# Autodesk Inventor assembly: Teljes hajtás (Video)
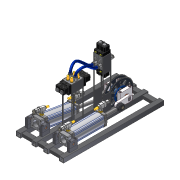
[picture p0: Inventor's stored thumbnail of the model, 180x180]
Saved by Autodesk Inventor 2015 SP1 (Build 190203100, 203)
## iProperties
Created: 2013-02
Part Number: Teljes hajtás (Video)
Document SubType Name: Assembly
Designer: Marci
Author: Marci
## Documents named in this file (19)
- C:\Users\TREINA11\Desktop\#01- Polymechanics and Automation\01 - 3D Models\Pneumatic System\Teljes hajtás (Video).iam
- C:\Users\TREINA11\Desktop\#01- Polymechanics and Automation\01 - 3D Models\Pneumatic System\Váz.iam
- C:\Users\TREINA11\Desktop\#01- Polymechanics and Automation\01 - 3D Models\Pneumatic System\Közdarab.ipt
- C:\Users\TREINA11\Desktop\#01- Polymechanics and Automation\01 - 3D Models\Pneumatic System\1827001604.ipt
- C:\Users\TREINA11\Desktop\#01- Polymechanics and Automation\01 - 3D Models\Pneumatic System\1827001611.ipt
- C:\Users\TREINA11\Desktop\#01- Polymechanics and Automation\01 - 3D Models\Pneumatic System\csapágyház.ipt
- C:\Users\TREINA11\Desktop\#01- Polymechanics and Automation\01 - 3D Models\Pneumatic System\Összerakva a henger.iam
- C:\Users\TREINA11\Desktop\#01- Polymechanics and Automation\01 - 3D Models\Pneumatic System\Főtengely összerakva.iam
- C:\Users\TREINA11\Desktop\#01- Polymechanics and Automation\01 - 3D Models\Pneumatic System\Szelep összerakva.iam
- C:\Users\TREINA11\Desktop\#01- Polymechanics and Automation\01 - 3D Models\Pneumatic System\Szelep.ipt
- C:\Users\TREINA11\Desktop\#01- Polymechanics and Automation\01 - 3D Models\Pneumatic System\1.4 12 gyorscsat.ipt
- C:\Users\TREINA11\Desktop\#01- Polymechanics and Automation\01 - 3D Models\Pneumatic System\Zárócsavar.ipt
- C:\Users\TREINA11\Desktop\#01- Polymechanics and Automation\01 - 3D Models\Pneumatic System\Lemez.ipt
- C:\Users\TREINA11\Desktop\#01- Polymechanics and Automation\01 - 3D Models\Pneumatic System\Lemez 2.ipt
- C:\Users\TREINA11\Desktop\#01- Polymechanics and Automation\01 - 3D Models\Pneumatic System\Teljes hajtás.Tube and Pipe Runs05.iam
- C:\Users\TREINA11\Desktop\#01- Polymechanics and Automation\01 - 3D Models\Pneumatic System\Atuador.iam
- C:\Users\TREINA11\Desktop\#01- Polymechanics and Automation\01 - 3D Models\Pneumatic System\Eixo.ipt
- C:\Users\TREINA11\Desktop\#01- Polymechanics and Automation\01 - 3D Models\Pneumatic System\Ponta.ipt
- C:\Users\TREINA11\Desktop\#01- Polymechanics and Automation\01 - 3D Models\Pneumatic System\DIN 912 - M8 x 1,25 x 30 x 26,875.ipt
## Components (69 placed, 18 different names)
1. Váz:1 [sub-assembly] — Flush:1, Mate:1, Flush:2, Mate:2, Flush:3, Flush:4, Mate:3, Flush:5, Flush:6, Mate:4, Flush:7, Flush:8, Mate:14, Mate:15, Flush:17, Flush:18, Flush:19, Flush:20, Flush:25, Mate:30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
2. Közdarab:1 — Flush:1, Mate:1, Flush:2, Mate:5, Flush:9, Flush:10
3. Közdarab:2 — Mate:2, Flush:3, Flush:4, Mate:6, Flush:11, Flush:12
4. Közdarab:3 — Mate:3, Flush:5, Flush:6, Flush:13, Mate:7, Flush:14
5. Közdarab:4 — Mate:4, Flush:7, Flush:8, Mate:8, Flush:16
6. 1827001604:1 — Mate:5, Flush:9, Flush:10, Mate:12, Mate:13, Inserir:19, Inserir:22
7. 1827001604:2 — Mate:6, Flush:11, Flush:12, Mate:29, Inserir:20, Inserir:21
8. 1827001604:3 — Flush:13, Mate:7, Flush:14, Mate:9, Mate:10, Inserir:23, Inserir:24
9. 1827001604:4 — Mate:8, Flush:16, Mate:11, Inserir:25, Inserir:26
10. 1827001611:1 — Mate:9, Mate:10, Mate:11, Insert:15, Insert:16, Insert:17, Insert:18, Mate:67, Mate:68, Angle:2
11. 1827001611:2 — Mate:12, Mate:13, Mate:59, Mate:60, Angle:1, Insert:2, Insert:3, Insert:4, Insert:5
12. csapágyház:1 — Mate:14, Flush:18, Flush:20, Mate:22, Mate:23, Inserir:29, Inserir:30
13. csapágyház:2 — Mate:15, Flush:17, Flush:19, Inserir:27, Inserir:28
14. Összerakva a henger:1 [sub-assembly] — Mate:61, Mate:62, Mate:63
15. Összerakva a henger:2 [sub-assembly] — Mate:69, Mate:70, Mate:72
16. Főtengely összerakva:1 [sub-assembly] — Mate:22, Mate:23, Mate:65, Mate:71, MOTOR
17. Szelep összerakva:1 [sub-assembly] — Mate:28, Mate:29, Mate:30, Flush:27, Flush:28, Flush:30, Mate:55, Mate:56
18. Szelep összerakva:2 [sub-assembly] — Flush:26, Flush:27, Flush:28, Flush:29, Mate:58
19. Szelep:1 — Flush:31, Mate:31, Flush:32, Mate:34, Mate:35, Mate:36, Mate:38, Mate:40, Mate:42, Mate:44, Mate:47, Mate:48, Mate:51, Mate:54, Flush:34
20. Szelep:2 — Flush:29, Flush:30, Flush:31, Mate:31, Flush:32, Mate:32, Mate:33, Mate:37, Mate:39, Mate:41, Mate:43, Mate:45, Mate:46, Mate:49, Mate:50, Mate:52, Flush:33
21. 1.4 12 gyorscsat:1 — Mate:32, Mate:33
22. 1.4 12 gyorscsat:2 — Mate:34, Mate:35
23. 1.4 12 gyorscsat:3 — Mate:36, Mate:38
24. 1.4 12 gyorscsat:4 — Mate:37, Mate:39
25. Zárócsavar:1 — Mate:46, Mate:49
26. Zárócsavar:2 — Mate:47, Mate:48
27. Zárócsavar:3 — Mate:40, Mate:51
28. Zárócsavar:4 — Mate:41, Mate:50
29. Zárócsavar:5 — Mate:43, Mate:45
30. Zárócsavar:6 — Mate:42, Mate:44
31. Lemez:1 — Mate:52, Flush:33, Mate:53, Flush:35
32. Lemez:2 — Mate:54, Flush:34, Flush:35, Flush:38
33. Lemez 2:1 — Mate:55, Mate:56, Mate:57, Flush:36, Flush:37
34. Lemez 2:2 — Flush:36, Mate:58, Flush:37
35. Tube & Pipe Runs 05 [sub-assembly]
36. Atuador:1 [sub-assembly] — Mate:59, Mate:60, Mate:61, Mate:62, Mate:63, Angle:1, Mate:64, Insert:6, Insert:7, Insert:8, Insert:9, Mate:75
37. Eixo:1 — Mate:64, Insert:1, Mate:75
38. Ponta:1 — Insert:1, Mate:65
39. DIN 912 - M8 x 1,25 x 30 x 26,875:1 — Insert:2
40. DIN 912 - M8 x 1,25 x 30 x 26,875:2 — Insert:3
41. DIN 912 - M8 x 1,25 x 30 x 26,875:3 — Insert:4
42. DIN 912 - M8 x 1,25 x 30 x 26,875:4 — Insert:5
43. DIN 912 - M8 x 1,25 x 30 x 26,875:5 — Insert:6
44. DIN 912 - M8 x 1,25 x 30 x 26,875:6 — Insert:7
45. DIN 912 - M8 x 1,25 x 30 x 26,875:7 — Insert:9
46. DIN 912 - M8 x 1,25 x 30 x 26,875:8 — Insert:8
47. Atuador:2 [sub-assembly] — Mate:67, Mate:68, Mate:69, Mate:70, Angle:2, Mate:72
48. Eixo:2
49. Ponta:2 — Mate:71
50. DIN 912 - M8 x 1,25 x 30 x 26,875:9 — Insert:16
51. DIN 912 - M8 x 1,25 x 30 x 26,875:10 — Insert:17
52. DIN 912 - M8 x 1,25 x 30 x 26,875:11 — Insert:18
53. DIN 912 - M8 x 1,25 x 30 x 26,875:12 — Insert:15
54. DIN 912 - M8 x 1,25 x 30 x 26,875:13
55. DIN 912 - M8 x 1,25 x 30 x 26,875:14
56. DIN 912 - M8 x 1,25 x 30 x 26,875:15
57. DIN 912 - M8 x 1,25 x 30 x 26,875:16
58. DIN 912 - M8 x 1,25 x 30 x 26,875:17 — Inserir:19
59. DIN 912 - M8 x 1,25 x 30 x 26,875:18 — Inserir:23
60. DIN 912 - M8 x 1,25 x 30 x 26,875:19 — Inserir:20
61. DIN 912 - M8 x 1,25 x 30 x 26,875:20 — Inserir:21
62. DIN 912 - M8 x 1,25 x 30 x 26,875:21 — Inserir:22
63. DIN 912 - M8 x 1,25 x 30 x 26,875:22 — Inserir:24
64. DIN 912 - M8 x 1,25 x 30 x 26,875:23 — Inserir:25
65. DIN 912 - M8 x 1,25 x 30 x 26,875:24 — Inserir:26
66. DIN 912 - M8 x 1,25 x 30 x 26,875:25 — Inserir:29
67. DIN 912 - M8 x 1,25 x 30 x 26,875:26 — Inserir:30
68. DIN 912 - M8 x 1,25 x 30 x 26,875:27 — Inserir:27
69. DIN 912 - M8 x 1,25 x 30 x 26,875:28 — Inserir:28
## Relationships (126: Mate 64, Flush 34, Insert 25, Angle 3)
- Flush:1: Váz:1 ↔ Közdarab:1
- Mate:1: Váz:1 ↔ Közdarab:1
- Flush:2: Váz:1 ↔ Közdarab:1
- Mate:2: Váz:1 ↔ Közdarab:2
- Flush:3: Váz:1 ↔ Közdarab:2
- Flush:4: Váz:1 ↔ Közdarab:2
- Mate:3: Váz:1 ↔ Közdarab:3
- Flush:5: Váz:1 ↔ Közdarab:3
- Flush:6: Váz:1 ↔ Közdarab:3
- Mate:4: Váz:1 ↔ Közdarab:4
- Flush:7: Váz:1 ↔ Közdarab:4
- Flush:8: Váz:1 ↔ Közdarab:4
- Mate:5: Közdarab:1 ↔ 1827001604:1
- Flush:9: Közdarab:1 ↔ 1827001604:1
- Flush:10: Közdarab:1 ↔ 1827001604:1
- Mate:6: Közdarab:2 ↔ 1827001604:2
- Flush:11: Közdarab:2 ↔ 1827001604:2
- Flush:12: Közdarab:2 ↔ 1827001604:2
- Flush:13: Közdarab:3 ↔ 1827001604:3
- Mate:7: Közdarab:3 ↔ 1827001604:3
- Flush:14: Közdarab:3 ↔ 1827001604:3
- Mate:8: Közdarab:4 ↔ 1827001604:4
- Flush:16: Közdarab:4 ↔ 1827001604:4
- Mate:9: 1827001604:3 ↔ 1827001611:1
- Mate:10: 1827001604:3 ↔ 1827001611:1
- Mate:11: 1827001604:4 ↔ 1827001611:1
- Mate:12: 1827001604:1 ↔ 1827001611:2
- Mate:13: 1827001604:1 ↔ 1827001611:2
- Mate:14: Váz:1 ↔ csapágyház:1
- Mate:15: Váz:1 ↔ csapágyház:2
- Flush:17: Váz:1 ↔ csapágyház:2
- Flush:18: Váz:1 ↔ csapágyház:1
- Flush:19: Váz:1 ↔ csapágyház:2
- Flush:20: Váz:1 ↔ csapágyház:1
- Mate:22: csapágyház:1 ↔ Főtengely összerakva:1
- Mate:23: csapágyház:1 ↔ Főtengely összerakva:1
- Flush:25: Váz:1
- Mate:28: Szelep összerakva:1
- Mate:29: 1827001604:2 ↔ Szelep összerakva:1
- Mate:30: Váz:1 ↔ Szelep összerakva:1
- Flush:26: Szelep összerakva:2
- Flush:27: Szelep összerakva:1 ↔ Szelep összerakva:2
- Flush:28: Szelep összerakva:1 ↔ Szelep összerakva:2
- Flush:29: Szelep összerakva:2 ↔ Szelep:2
- Flush:30: Szelep összerakva:1 ↔ Szelep:2
- Flush:31: Szelep:1 ↔ Szelep:2
- Mate:31: Szelep:1 ↔ Szelep:2
- Flush:32: Szelep:1 ↔ Szelep:2
- Mate:32: Szelep:2 ↔ 1.4 12 gyorscsat:1
- Mate:33: Szelep:2 ↔ 1.4 12 gyorscsat:1
- Mate:34: Szelep:1 ↔ 1.4 12 gyorscsat:2
- Mate:35: Szelep:1 ↔ 1.4 12 gyorscsat:2
- Mate:36: Szelep:1 ↔ 1.4 12 gyorscsat:3
- Mate:37: Szelep:2 ↔ 1.4 12 gyorscsat:4
- Mate:38: Szelep:1 ↔ 1.4 12 gyorscsat:3
- Mate:39: Szelep:2 ↔ 1.4 12 gyorscsat:4
- Mate:40: Szelep:1 ↔ Zárócsavar:3
- Mate:41: Szelep:2 ↔ Zárócsavar:4
- Mate:42: Szelep:1 ↔ Zárócsavar:6
- Mate:43: Szelep:2 ↔ Zárócsavar:5
- Mate:44: Szelep:1 ↔ Zárócsavar:6
- Mate:45: Szelep:2 ↔ Zárócsavar:5
- Mate:46: Szelep:2 ↔ Zárócsavar:1
- Mate:47: Szelep:1 ↔ Zárócsavar:2
- Mate:48: Szelep:1 ↔ Zárócsavar:2
- Mate:49: Szelep:2 ↔ Zárócsavar:1
- Mate:50: Szelep:2 ↔ Zárócsavar:4
- Mate:51: Szelep:1 ↔ Zárócsavar:3
- Mate:52: Szelep:2 ↔ Lemez:1
- Flush:33: Szelep:2 ↔ Lemez:1
- Mate:53: Váz:1 ↔ Lemez:1
- Mate:54: Szelep:1 ↔ Lemez:2
- Flush:34: Szelep:1 ↔ Lemez:2
- Flush:35: Lemez:1 ↔ Lemez:2
- Mate:55: Szelep összerakva:1 ↔ Lemez 2:1
- Mate:56: Szelep összerakva:1 ↔ Lemez 2:1
- Mate:57: Váz:1 ↔ Lemez 2:1
- Flush:36: Lemez 2:1 ↔ Lemez 2:2
- Mate:58: Szelep összerakva:2 ↔ Lemez 2:2
- Flush:37: Lemez 2:1 ↔ Lemez 2:2
- Mate:59: 1827001611:2 ↔ Atuador:1
- Mate:60: 1827001611:2 ↔ Atuador:1
- Mate:61: Összerakva a henger:1 ↔ Atuador:1
- Mate:62: Összerakva a henger:1 ↔ Atuador:1
- Mate:63: Összerakva a henger:1 ↔ Atuador:1
- Angle:1: 1827001611:2 ↔ Atuador:1
- Mate:64: Atuador:1 ↔ Eixo:1
- Insert:1: Eixo:1 ↔ Ponta:1
- Mate:65: Főtengely összerakva:1 ↔ Ponta:1
- Insert:2: 1827001611:2 ↔ DIN 912 - M8 x 1,25 x 30 x 26,875:1
- Insert:3: 1827001611:2 ↔ DIN 912 - M8 x 1,25 x 30 x 26,875:2
- Insert:4: 1827001611:2 ↔ DIN 912 - M8 x 1,25 x 30 x 26,875:3
- Insert:5: 1827001611:2 ↔ DIN 912 - M8 x 1,25 x 30 x 26,875:4
- Insert:6: Atuador:1 ↔ DIN 912 - M8 x 1,25 x 30 x 26,875:5
- Insert:7: Atuador:1 ↔ DIN 912 - M8 x 1,25 x 30 x 26,875:6
- Insert:8: Atuador:1 ↔ DIN 912 - M8 x 1,25 x 30 x 26,875:8
- Insert:9: Atuador:1 ↔ DIN 912 - M8 x 1,25 x 30 x 26,875:7
- Insert:15: 1827001611:1 ↔ DIN 912 - M8 x 1,25 x 30 x 26,875:12
- Insert:16: 1827001611:1 ↔ DIN 912 - M8 x 1,25 x 30 x 26,875:9
- Insert:17: 1827001611:1 ↔ DIN 912 - M8 x 1,25 x 30 x 26,875:10
- Insert:18: 1827001611:1 ↔ DIN 912 - M8 x 1,25 x 30 x 26,875:11
- Mate:67: 1827001611:1 ↔ Atuador:2
- Mate:68: 1827001611:1 ↔ Atuador:2
- Mate:69: Összerakva a henger:2 ↔ Atuador:2
- Mate:70: Összerakva a henger:2 ↔ Atuador:2
- Mate:71: Főtengely összerakva:1 ↔ Ponta:2
- Angle:2: 1827001611:1 ↔ Atuador:2
- Mate:72: Összerakva a henger:2 ↔ Atuador:2
- MOTOR [Angle]: Váz:1 ↔ Főtengely összerakva:1
- Inserir:19: 1827001604:1 ↔ DIN 912 - M8 x 1,25 x 30 x 26,875:17
- Inserir:20: 1827001604:2 ↔ DIN 912 - M8 x 1,25 x 30 x 26,875:19
- Inserir:21: 1827001604:2 ↔ DIN 912 - M8 x 1,25 x 30 x 26,875:20
- Inserir:22: 1827001604:1 ↔ DIN 912 - M8 x 1,25 x 30 x 26,875:21
- Inserir:23: 1827001604:3 ↔ DIN 912 - M8 x 1,25 x 30 x 26,875:18
- Inserir:24: 1827001604:3 ↔ DIN 912 - M8 x 1,25 x 30 x 26,875:22
- Inserir:25: 1827001604:4 ↔ DIN 912 - M8 x 1,25 x 30 x 26,875:23
- Inserir:26: 1827001604:4 ↔ DIN 912 - M8 x 1,25 x 30 x 26,875:24
- Inserir:27: csapágyház:2 ↔ DIN 912 - M8 x 1,25 x 30 x 26,875:27
- Inserir:28: csapágyház:2 ↔ DIN 912 - M8 x 1,25 x 30 x 26,875:28
- Inserir:29: csapágyház:1 ↔ DIN 912 - M8 x 1,25 x 30 x 26,875:25
- Inserir:30: csapágyház:1 ↔ DIN 912 - M8 x 1,25 x 30 x 26,875:26
- Flush:38: Váz:1 ↔ Lemez:2
- Mate:73: Váz:1
- Flush:39: Váz:1
- Mate:74: Váz:1
- Mate:75: Atuador:1 ↔ Eixo:1
## Named parameters: d116_d105 = 0, d117_d106 = 0, d118_d112 = 0, d119_d113 = 0, d120_d114 = 0, d121_d115 = 0
